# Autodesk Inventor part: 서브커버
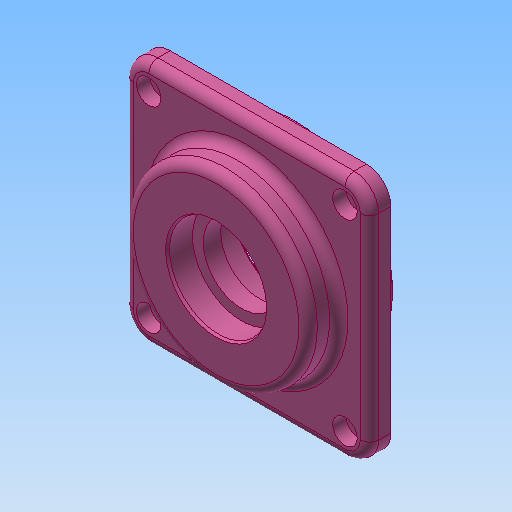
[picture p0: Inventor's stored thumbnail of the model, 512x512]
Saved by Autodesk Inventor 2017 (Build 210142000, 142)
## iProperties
Created: 2018-09
Part Number: 서브커버
Material: 알루미늄 6061
Document SubType Name: Modeling
Designer: mduedu
Density: 2.71 g/cm^3
Mass: 206.54 g
Surface Area: 196.569 cm^2
Volume: 76.2142 cm^3
Appearance: 분홍색
Author: mduedu
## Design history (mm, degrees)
sketch "스케치1"
  geometry: L1 (-40, -40)-(40, -40); L2 (40, -40)-(40, 40); L3 (40, 40)-(-40, 40); L4 (-40, 40)-(-40, -40); L5 (-40, -40)-(40, 40); L6 (40, -40)-(-40, 40); 1 further point
  constraints: 12 end point, 2 midpoint, 2 parallel, 1 horizontal, 1 perpendicular
  dimensions: "d0" = 80 distance of L3.end L2.end; "d1" = 80 distance of L2.end L1.end
extrude "돌출1" new body sketch "스케치1" distance "d2" = 7; taper "d3" = 0 deg
sketch "스케치2"
  geometry: C1 r 30 at (0, 0); 1 further point
  constraints: 1 centre point, 1 coincident
  dimensions: "d4" = 60 diameter of C1
extrude "돌출2" join sketch "스케치2" distance "d5" = 10; taper "d6" = 0 deg
sketch "스케치3"
  geometry: C1 r 32.5 at (0, 0); 1 further point
  constraints: 1 centre point, 1 coincident
  dimensions: "d7" = 65 diameter of C1
extrude "돌출3" join sketch "스케치3" distance "d8" = 9; taper "d9" = 0 deg
sketch "스케치4"
  geometry: L1 (-32.5, -9)-(32.5, -9) reference; L2 (30, 17)-(-30, 17) reference; L3 (0, 17)-(0, -9); L4 (0, -9)-(20, -9); L5 (20, -9)-(20, 3); L6 (20, 3)-(0, 3); L7 (0, 3)-(0, -9); L8 (0, 3)-(12.5, 3); L9 (12.5, 3)-(12.5, 8.7); L10 (12.5, 8.7)-(0, 8.7); L11 (0, 8.7)-(0, 3); L12 (0, 8.7)-(16, 8.7); L13 (16, 8.7)-(16, 17); L14 (16, 17)-(0, 17); L15 (0, 17)-(0, 8.7); 1 further point
  constraints: 26 end point, 6 parallel, 3 horizontal, 3 perpendicular, 2 midpoint, 1 point on line
  dimensions: "d10" = 12 distance of L4.end L5.end; "d12" = 8.3 distance of L12.end L13.end; "d13" = 32 diameter of L13 L3; "d14" = 25 diameter of L9 L3; "d15" = 40 diameter of L5 L3
revolve "회전1" sketch "스케치4" stored, may be unused: angle "d16" = 90 deg
fillet "모깎기1" dims "d17" = 8
fillet "모깎기2" dims "d18" = 3
fillet "모깎기3" dims "d19" = 3
chamfer "모따기1" distance "d20" = 0.8; stored, may be unused: second distance "d21" = 2, angle "d22" = 30 deg
chamfer "모따기2" distance "d23" = 1; stored, may be unused: second distance "d24" = 2, angle "d25" = 30 deg
fillet "모깎기4" dims "d26" = 0.3
sketch "스케치5"
  geometry: A1 r 8 centre (-32, 32) between (-32, 40) and (-40, 32) reference; A2 r 8 centre (-32, -32) between (-40, -32) and (-32, -40) reference; A3 r 8 centre (32, -32) between (32, -40) and (40, -32) reference; A4 r 8 centre (32, 32) between (40, 32) and (32, 40) reference; 5 further points
  constraints: 4 coincident
hole "구멍1" sketch "스케치5" at (-32, 32), (32, 32), (32, -32), (-32, -32) diameter "d27" = 4.5; stored, may be unused: countersink angle "d31" = 90 deg, drill point angle "d33" = 118 deg; dims "d28" = 6, "d29" = 8, "d30" = 4.4, "d32" = 8
fillet "모깎기5" dims "d34" = 0.5
node "솔리드1"
